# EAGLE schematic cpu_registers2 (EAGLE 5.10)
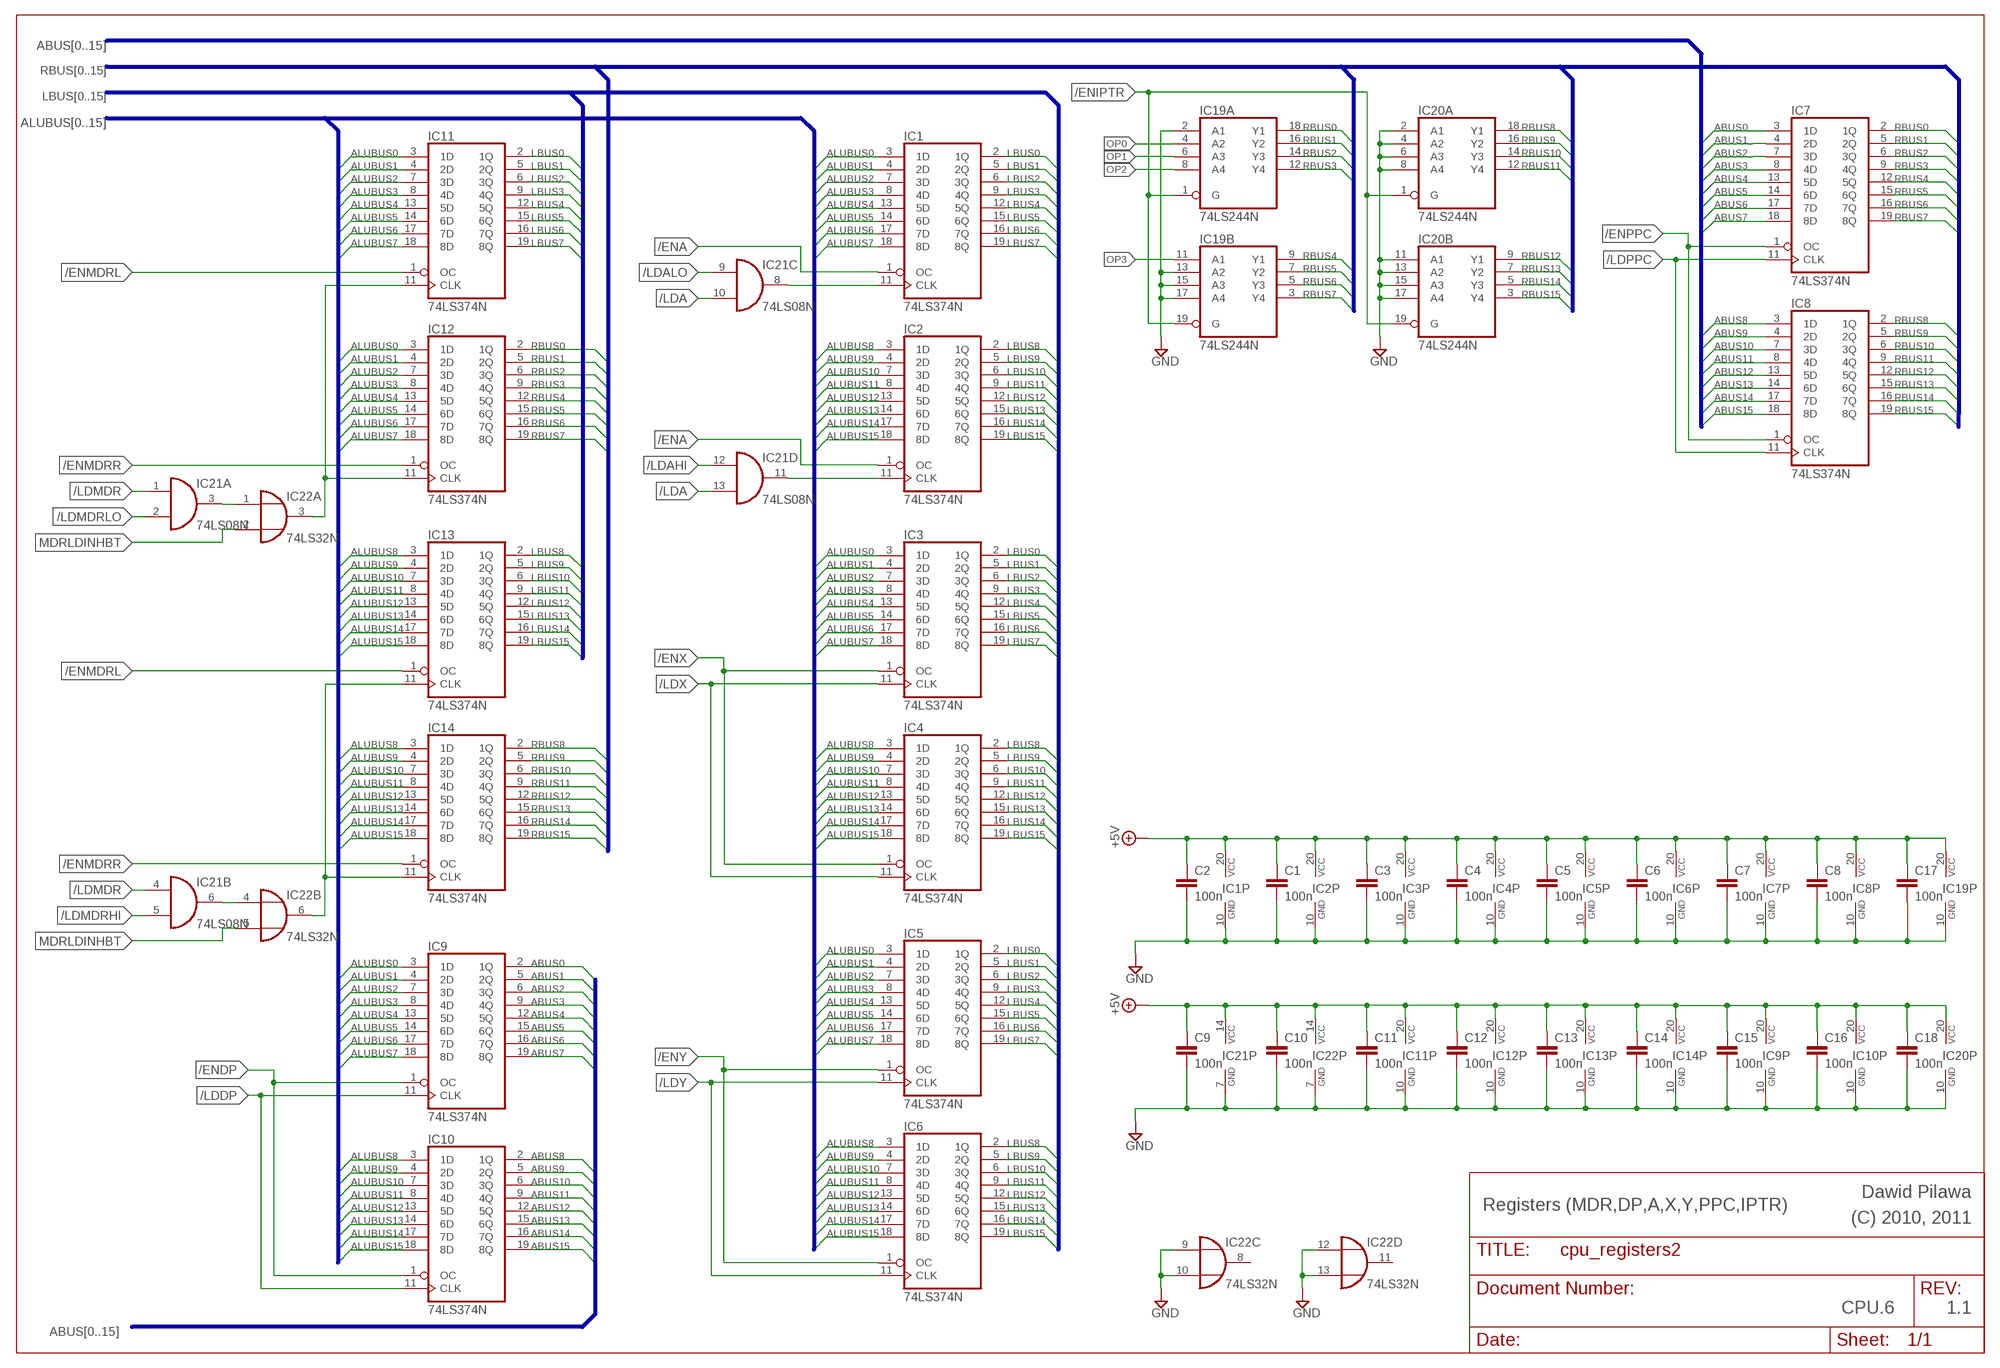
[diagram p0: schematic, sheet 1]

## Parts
C1  100n  C-EU050-024X044  [C050-024X044]
C2  100n  C-EU050-024X044  [C050-024X044]
C3  100n  C-EU050-024X044  [C050-024X044]
C4  100n  C-EU050-024X044  [C050-024X044]
C5  100n  C-EU050-024X044  [C050-024X044]
C6  100n  C-EU050-024X044  [C050-024X044]
C7  100n  C-EU050-024X044  [C050-024X044]
C8  100n  C-EU050-024X044  [C050-024X044]
C9  100n  C-EU050-024X044  [C050-024X044]
C10  100n  C-EU050-024X044  [C050-024X044]
C11  100n  C-EU050-024X044  [C050-024X044]
C12  100n  C-EU050-024X044  [C050-024X044]
C13  100n  C-EU050-024X044  [C050-024X044]
C14  100n  C-EU050-024X044  [C050-024X044]
C15  100n  C-EU050-024X044  [C050-024X044]
C16  100n  C-EU050-024X044  [C050-024X044]
C17  100n  C-EU050-024X044  [C050-024X044]
C18  100n  C-EU050-024X044  [C050-024X044]
IC1  74LS374N  [DIL20]
IC2  74LS374N  [DIL20]
IC3  74LS374N  [DIL20]
IC4  74LS374N  [DIL20]
IC5  74LS374N  [DIL20]
IC6  74LS374N  [DIL20]
IC7  74LS374N  [DIL20]
IC8  74LS374N  [DIL20]
IC9  74LS374N  [DIL20]
IC10  74LS374N  [DIL20]
IC11  74LS374N  [DIL20]
IC12  74LS374N  [DIL20]
IC13  74LS374N  [DIL20]
IC14  74LS374N  [DIL20]
IC19  74LS244N  [DIL20]
IC20  74LS244N  [DIL20]
IC21  74LS08N  [DIL14]
IC22  74LS32N  [DIL14]

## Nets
+5V: C1.1 C2.1 C3.1 C4.1 C5.1 C6.1 C7.1 C8.1 C9.1 C10.1 C11.1 C12.1 C13.1 C14.1 C15.1 C16.1 C17.1 C18.1 IC1.20(VCC) IC2.20(VCC) IC3.20(VCC) IC4.20(VCC) IC5.20(VCC) IC6.20(VCC) IC7.20(VCC) IC8.20(VCC) IC9.20(VCC) IC10.20(VCC) IC11.20(VCC) IC12.20(VCC) IC13.20(VCC) IC14.20(VCC) IC19.20(P:VCC) IC20.20(P:VCC) IC21.14(P:VCC) IC22.14(P:VCC)
/ENA: IC1.1(OC) IC2.1(OC)
/ENDP: IC9.1(OC) IC10.1(OC)
/ENIPTR: IC19.1(A:G) IC19.19(B:G) IC20.1(A:G) IC20.19(B:G)
/ENMDRL: IC11.1(OC) IC13.1(OC)
/ENMDRR: IC12.1(OC) IC14.1(OC)
/ENPPC: IC7.1(OC) IC8.1(OC)
/ENX: IC3.1(OC) IC4.1(OC)
/ENY: IC5.1(OC) IC6.1(OC)
/LDA: IC21.10(C:I1) IC21.13(D:I1)
/LDAHI: IC21.12(D:I0)
/LDALO: IC21.9(C:I0)
/LDDP: IC9.11(CLK) IC10.11(CLK)
/LDMDR: IC21.1(A:I0) IC21.4(B:I0)
/LDMDRHI: IC21.5(B:I1)
/LDMDRLO: IC21.2(A:I1)
/LDPPC: IC7.11(CLK) IC8.11(CLK)
/LDX: IC3.11(CLK) IC4.11(CLK)
/LDY: IC5.11(CLK) IC6.11(CLK)
ABUS0: IC7.3(1D) IC9.2(1Q)
ABUS1: IC7.4(2D) IC9.5(2Q)
ABUS2: IC7.7(3D) IC9.6(3Q)
ABUS3: IC7.8(4D) IC9.9(4Q)
ABUS4: IC7.13(5D) IC9.12(5Q)
ABUS5: IC7.14(6D) IC9.15(6Q)
ABUS6: IC7.17(7D) IC9.16(7Q)
ABUS7: IC7.18(8D) IC9.19(8Q)
ABUS8: IC8.3(1D) IC10.2(1Q)
ABUS9: IC8.4(2D) IC10.5(2Q)
ABUS10: IC8.7(3D) IC10.6(3Q)
ABUS11: IC8.8(4D) IC10.9(4Q)
ABUS12: IC8.13(5D) IC10.12(5Q)
ABUS13: IC8.14(6D) IC10.15(6Q)
ABUS14: IC8.17(7D) IC10.16(7Q)
ABUS15: IC8.18(8D) IC10.19(8Q)
ALUBUS0: IC1.3(1D) IC3.3(1D) IC5.3(1D) IC9.3(1D) IC11.3(1D) IC12.3(1D)
ALUBUS1: IC1.4(2D) IC3.4(2D) IC5.4(2D) IC9.4(2D) IC11.4(2D) IC12.4(2D)
ALUBUS2: IC1.7(3D) IC3.7(3D) IC5.7(3D) IC9.7(3D) IC11.7(3D) IC12.7(3D)
ALUBUS3: IC1.8(4D) IC3.8(4D) IC5.8(4D) IC9.8(4D) IC11.8(4D) IC12.8(4D)
ALUBUS4: IC1.13(5D) IC3.13(5D) IC5.13(5D) IC9.13(5D) IC11.13(5D) IC12.13(5D)
ALUBUS5: IC1.14(6D) IC3.14(6D) IC5.14(6D) IC9.14(6D) IC11.14(6D) IC12.14(6D)
ALUBUS6: IC1.17(7D) IC3.17(7D) IC5.17(7D) IC9.17(7D) IC11.17(7D) IC12.17(7D)
ALUBUS7: IC1.18(8D) IC3.18(8D) IC5.18(8D) IC9.18(8D) IC11.18(8D) IC12.18(8D)
ALUBUS8: IC2.3(1D) IC4.3(1D) IC6.3(1D) IC10.3(1D) IC13.3(1D) IC14.3(1D)
ALUBUS9: IC2.4(2D) IC4.4(2D) IC6.4(2D) IC10.4(2D) IC13.4(2D) IC14.4(2D)
ALUBUS10: IC2.7(3D) IC4.7(3D) IC6.7(3D) IC10.7(3D) IC13.7(3D) IC14.7(3D)
ALUBUS11: IC2.8(4D) IC4.8(4D) IC6.8(4D) IC10.8(4D) IC13.8(4D) IC14.8(4D)
ALUBUS12: IC2.13(5D) IC4.13(5D) IC6.13(5D) IC10.13(5D) IC13.13(5D) IC14.13(5D)
ALUBUS13: IC2.14(6D) IC4.14(6D) IC6.14(6D) IC10.14(6D) IC13.14(6D) IC14.14(6D)
ALUBUS14: IC2.17(7D) IC4.17(7D) IC6.17(7D) IC10.17(7D) IC13.17(7D) IC14.17(7D)
ALUBUS15: IC2.18(8D) IC4.18(8D) IC6.18(8D) IC10.18(8D) IC13.18(8D) IC14.18(8D)
GND: C1.2 C2.2 C3.2 C4.2 C5.2 C6.2 C7.2 C8.2 C9.2 C10.2 C11.2 C12.2 C13.2 C14.2 C15.2 C16.2 C17.2 C18.2 IC1.10(GND) IC2.10(GND) IC3.10(GND) IC4.10(GND) IC5.10(GND) IC6.10(GND) IC7.10(GND) IC8.10(GND) IC9.10(GND) IC10.10(GND) IC11.10(GND) IC12.10(GND) IC13.10(GND) IC14.10(GND) IC19.2(A:A1) IC19.10(P:GND) IC19.13(B:A2) IC19.15(B:A3) IC19.17(B:A4) IC20.2(A:A1) IC20.4(A:A2) IC20.6(A:A3) IC20.8(A:A4) IC20.10(P:GND) IC20.11(B:A1) IC20.13(B:A2) IC20.15(B:A3) IC20.17(B:A4) IC21.7(P:GND) IC22.7(P:GND) IC22.9(C:I0) IC22.10(C:I1) IC22.12(D:I0) IC22.13(D:I1)
LBUS0: IC1.2(1Q) IC3.2(1Q) IC5.2(1Q) IC11.2(1Q)
LBUS1: IC1.5(2Q) IC3.5(2Q) IC5.5(2Q) IC11.5(2Q)
LBUS2: IC1.6(3Q) IC3.6(3Q) IC5.6(3Q) IC11.6(3Q)
LBUS3: IC1.9(4Q) IC3.9(4Q) IC5.9(4Q) IC11.9(4Q)
LBUS4: IC1.12(5Q) IC3.12(5Q) IC5.12(5Q) IC11.12(5Q)
LBUS5: IC1.15(6Q) IC3.15(6Q) IC5.15(6Q) IC11.15(6Q)
LBUS6: IC1.16(7Q) IC3.16(7Q) IC5.16(7Q) IC11.16(7Q)
LBUS7: IC1.19(8Q) IC3.19(8Q) IC5.19(8Q) IC11.19(8Q)
LBUS8: IC2.2(1Q) IC4.2(1Q) IC6.2(1Q) IC13.2(1Q)
LBUS9: IC2.5(2Q) IC4.5(2Q) IC6.5(2Q) IC13.5(2Q)
LBUS10: IC2.6(3Q) IC4.6(3Q) IC6.6(3Q) IC13.6(3Q)
LBUS11: IC2.9(4Q) IC4.9(4Q) IC6.9(4Q) IC13.9(4Q)
LBUS12: IC2.12(5Q) IC4.12(5Q) IC6.12(5Q) IC13.12(5Q)
LBUS13: IC2.15(6Q) IC4.15(6Q) IC6.15(6Q) IC13.15(6Q)
LBUS14: IC2.16(7Q) IC4.16(7Q) IC6.16(7Q) IC13.16(7Q)
LBUS15: IC2.19(8Q) IC4.19(8Q) IC6.19(8Q) IC13.19(8Q)
MDRLDINHBT: IC22.2(A:I1) IC22.5(B:I1)
N$1: IC11.11(CLK) IC12.11(CLK) IC22.3(A:O)
N$3: IC21.3(A:O) IC22.1(A:I0)
N$4: IC21.6(B:O) IC22.4(B:I0)
N$5: IC13.11(CLK) IC14.11(CLK) IC22.6(B:O)
N$21: IC1.11(CLK) IC21.8(C:O)
N$22: IC2.11(CLK) IC21.11(D:O)
OP0: IC19.4(A:A2)
OP1: IC19.6(A:A3)
OP2: IC19.8(A:A4)
OP3: IC19.11(B:A1)
RBUS0: IC7.2(1Q) IC12.2(1Q) IC19.18(A:Y1)
RBUS1: IC7.5(2Q) IC12.5(2Q) IC19.16(A:Y2)
RBUS2: IC7.6(3Q) IC12.6(3Q) IC19.14(A:Y3)
RBUS3: IC7.9(4Q) IC12.9(4Q) IC19.12(A:Y4)
RBUS4: IC7.12(5Q) IC12.12(5Q) IC19.9(B:Y1)
RBUS5: IC7.15(6Q) IC12.15(6Q) IC19.7(B:Y2)
RBUS6: IC7.16(7Q) IC12.16(7Q) IC19.5(B:Y3)
RBUS7: IC7.19(8Q) IC12.19(8Q) IC19.3(B:Y4)
RBUS8: IC8.2(1Q) IC14.2(1Q) IC20.18(A:Y1)
RBUS9: IC8.5(2Q) IC14.5(2Q) IC20.16(A:Y2)
RBUS10: IC8.6(3Q) IC14.6(3Q) IC20.14(A:Y3)
RBUS11: IC8.9(4Q) IC14.9(4Q) IC20.12(A:Y4)
RBUS12: IC8.12(5Q) IC14.12(5Q) IC20.9(B:Y1)
RBUS13: IC8.15(6Q) IC14.15(6Q) IC20.7(B:Y2)
RBUS14: IC8.16(7Q) IC14.16(7Q) IC20.5(B:Y3)
RBUS15: IC8.19(8Q) IC14.19(8Q) IC20.3(B:Y4)
Unconnected: IC22.8(C:O) IC22.11(D:O)

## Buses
ALUBUS[0..15]
LBUS[0..15]
RBUS[0..15]
ABUS[0..15]

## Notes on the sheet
- Dawid Pilawa
- Registers (MDR,DP,A,X,Y,PPC,IPTR) | (C) 2010, 2011
- CPU.6 | 1.1

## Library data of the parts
C1-C18 = rcl:C-EU: CAPACITOR, European symbol
IC1-IC14 = 74xx-eu:74*374: Octal D type transparent LATCH, edge triggered
IC19 IC20 = 74xx-eu:74*244: Octal BUFFER and LINE DRIVER, 3-state
IC21 = 74xx-eu:74*08: Quad 2-input AND gate
IC22 = 74xx-eu:74*32: Quad 2-input OR gate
